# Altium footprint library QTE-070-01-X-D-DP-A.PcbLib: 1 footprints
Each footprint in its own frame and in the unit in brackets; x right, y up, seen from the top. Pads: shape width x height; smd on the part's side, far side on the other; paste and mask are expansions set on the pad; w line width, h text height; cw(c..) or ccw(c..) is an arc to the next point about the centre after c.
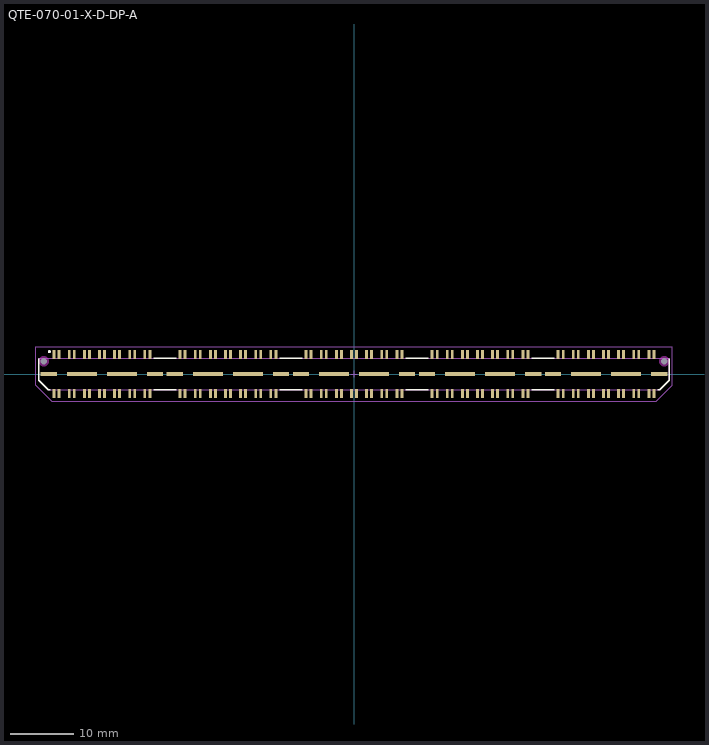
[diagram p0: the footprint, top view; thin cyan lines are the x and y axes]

## QTE-070-01-X-D-DP-A [mm] "0.80mm pitch, 140 pin, high speed terminal strip; differential"
height 4.27
pads (162):
  rect 0.45x1.45 smd mask+0: 1(-47.6,3.09) 2(-47.6,-3.09) 3(-46.8,3.09) 4(-46.8,-3.09) 5(-45.2,3.09) 6(-45.2,-3.09) 7(-44.4,3.09) 8(-44.4,-3.09) 9(-42.8,3.09) 10(-42.8,-3.09) 11(-42,3.09) 12(-42,-3.09) 13(-40.4,3.09) 14(-40.4,-3.09) 15(-39.6,3.09) 16(-39.6,-3.09) 17(-38,3.09) 18(-38,-3.09) 19(-37.2,3.09) 20(-37.2,-3.09) 21(-35.6,3.09) 22(-35.6,-3.09) 23(-34.8,3.09) 24(-34.8,-3.09) 25(-33.2,3.09) 26(-33.2,-3.09) 27(-32.4,3.09) 28(-32.4,-3.09) 29(-27.6,3.09) 30(-27.6,-3.09) 31(-26.8,3.09) 32(-26.8,-3.09) 33(-25.2,3.09) 34(-25.2,-3.09) 35(-24.4,3.09) 36(-24.4,-3.09) 37(-22.8,3.09) 38(-22.8,-3.09) 39(-22,3.09) 40(-22,-3.09) 41(-20.4,3.09) 42(-20.4,-3.09) 43(-19.6,3.09) 44(-19.6,-3.09) 45(-18,3.09) 46(-18,-3.09) 47(-17.2,3.09) 48(-17.2,-3.09) 49(-15.6,3.09) 50(-15.6,-3.09) 51(-14.8,3.09) 52(-14.8,-3.09) 53(-13.2,3.09) 54(-13.2,-3.09) 55(-12.4,3.09) 56(-12.4,-3.09) 57(-7.6,3.09) 58(-7.6,-3.09) 59(-6.8,3.09) 60(-6.8,-3.09) 61(-5.2,3.09) 62(-5.2,-3.09) 63(-4.4,3.09) 64(-4.4,-3.09) 65(-2.8,3.09) 66(-2.8,-3.09) 67(-2,3.09) 68(-2,-3.09) 69(-0.4,3.09) 70(-0.4,-3.09) 71(0.4,3.09) 72(0.4,-3.09) 73(2,3.09) 74(2,-3.09) 75(2.8,3.09) 76(2.8,-3.09) 77(4.4,3.09) 78(4.4,-3.09) 79(5.2,3.09) 80(5.2,-3.09) 81(6.8,3.09) 82(6.8,-3.09) 83(7.6,3.09) 84(7.6,-3.09) 85(12.4,3.09) 86(12.4,-3.09) 87(13.2,3.09) 88(13.2,-3.09) 89(14.8,3.09) 90(14.8,-3.09) 91(15.6,3.09) 92(15.6,-3.09) 93(17.2,3.09) 94(17.2,-3.09) 95(18,3.09) 96(18,-3.09) 97(19.6,3.09) 98(19.6,-3.09) 99(20.4,3.09) 100(20.4,-3.09) 101(22,3.09) 102(22,-3.09) 103(22.8,3.09) 104(22.8,-3.09) 105(24.4,3.09) 106(24.4,-3.09) 107(25.2,3.09) 108(25.2,-3.09) 109(26.8,3.09) 110(26.8,-3.09) 111(27.6,3.09) 112(27.6,-3.09) 113(32.4,3.09) 114(32.4,-3.09) 115(33.2,3.09) 116(33.2,-3.09) 117(34.8,3.09) 118(34.8,-3.09) 119(35.6,3.09) 120(35.6,-3.09) 121(37.2,3.09) 122(37.2,-3.09) 123(38,3.09) 124(38,-3.09) 125(39.6,3.09) 126(39.6,-3.09) 127(40.4,3.09) 128(40.4,-3.09) 129(42,3.09) 130(42,-3.09) 131(42.8,3.09) 132(42.8,-3.09) 133(44.4,3.09) 134(44.4,-3.09) 135(45.2,3.09) 136(45.2,-3.09) 137(46.8,3.09) 138(46.8,-3.09) 139(47.6,3.09) 140(47.6,-3.09)
  rect 2.55x0.65 smd mask+0: 141(-48.445,0) 144(-31.555,0) 145(-28.445,0) 148(-11.555,0) 149(-8.445,0) 152(8.445,0) 153(11.555,0) 156(28.445,0) 157(31.555,0) 160(48.445,0)
  rect 4.7x0.65 smd mask+0: 142(-43.175,0) 143(-36.825,0) 146(-23.175,0) 147(-16.825,0) 150(-3.175,0) 151(3.175,0) 154(16.825,0) 155(23.175,0) 158(36.825,0) 159(43.175,0)
  round 0.5 hole 1 unplated mask+0: 161(-49.24,2.04) 162(49.24,2.04)
Top Overlay:
  circle w0.25: c-48.35,3.55 r0.125
  lines w0.2: -50,2.45 -50,-1 -48.5,-2.5 -48.2,-2.5 ; -31.8,-2.5 -28.2,-2.5 ; -31.8,2.5 -28.2,2.5 ; -11.8,-2.5 -8.2,-2.5 ; -11.8,2.5 -8.2,2.5 ; 8.2,-2.5 11.8,-2.5 ; 8.25,2.5 11.75,2.5 ; 28.2,-2.5 31.8,-2.5 ; 28.2,2.5 31.8,2.5 ; 48.2,-2.5 48.5,-2.5 50,-1 50,2.45
Keep-Out Layer:
  pour cut-out: -48.433,2.04 -48.461,2.249 -48.541,2.443 -48.669,2.611 -48.837,2.739 -49.031,2.819 -49.24,2.847 -49.449,2.819 -49.643,2.739 -49.811,2.611 -49.939,2.443 -50.019,2.249 -50.047,2.04 -50.019,1.831 -49.939,1.637 -49.811,1.469 -49.643,1.341 -49.449,1.261 -49.24,1.233 -49.031,1.261 -48.837,1.341 -48.669,1.469 -48.541,1.637 -48.461,1.831
  pour cut-out: 50.047,2.04 50.019,2.249 49.939,2.443 49.811,2.611 49.643,2.739 49.449,2.819 49.24,2.847 49.031,2.819 48.837,2.739 48.669,2.611 48.541,2.443 48.461,2.249 48.433,2.04 48.461,1.831 48.541,1.637 48.669,1.469 48.837,1.341 49.031,1.261 49.24,1.233 49.449,1.261 49.643,1.341 49.811,1.469 49.939,1.637 50.019,1.831
Mechanical 13:
  lines w0.1: -50,-1 -48.5,-2.5 48.5,-2.5 50,-1 50,2.5 -50,2.5 -50,-1
  text ".Designator" at 0.254,0.254 h1.52
Mechanical 15:
  lines w0.05: -0.5,0 0.5,0 ; 0,-0.5 0,0.5 ; -50.5,-1.75 -47.95,-4.3 47.95,-4.3 50.5,-1.75 50.5,4.3 -50.5,4.3 -50.5,-1.75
